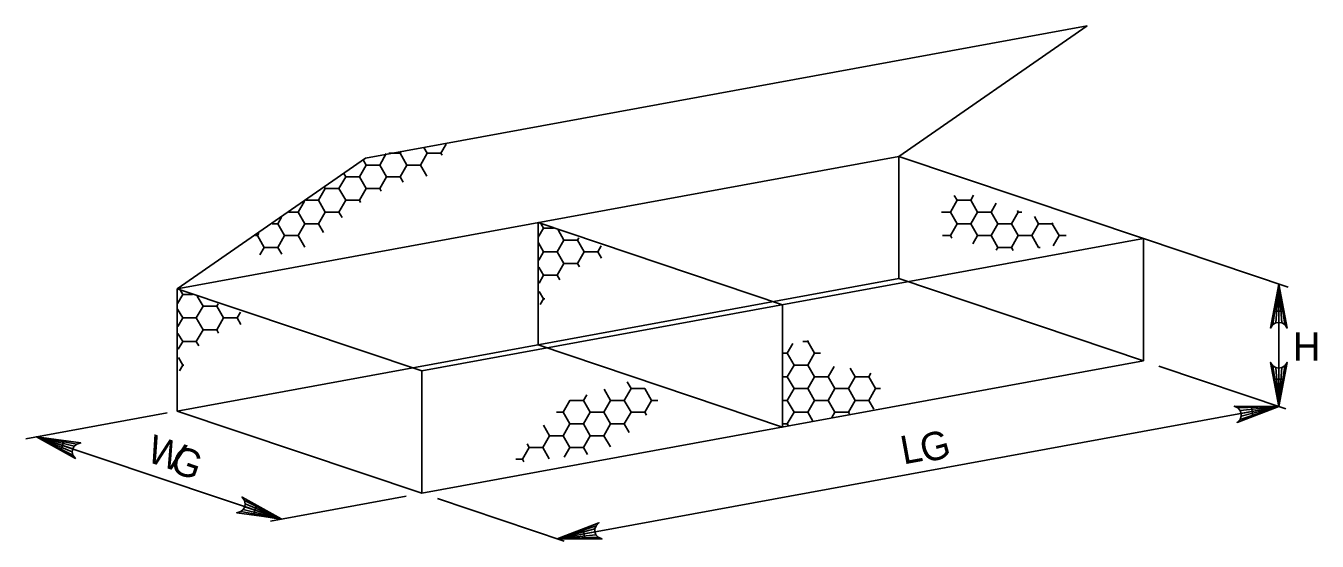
# Model space of a CAD drawing. Extents: x 638142 to 639291, y 297247 to 298438.
# Drawn here: x 638842.5 to 638979.6, y 297441.4 to 297496 of the extents above; entities that cross this region are included whole.
import ezdxf

# ---------------------------------------------------------------- set-up
doc = ezdxf.new("R2010")
doc.units = 0
doc.layers.add('3', color=7, linetype='Continuous')
doc.layers.add('5', color=7, linetype='Continuous')

msp = doc.modelspace()

# ---------------------------------------------------------------- linework, layer by layer
at = {"layer": '3'}
for p, q in [((638878.6, 297481.99), (638955.18, 297496.04)), ((638935.19, 297482.19), (638955.18, 297496.04)), ((638885.15, 297482.52), (638884.8, 297483.12)), ((638886.59, 297482.52), (638887.15, 297483.49)), ((638858.61, 297468.14), (638935.19, 297482.19)), ((638858.61, 297468.14), (638878.6, 297481.99)), ((638878.66, 297481.27), (638878.35, 297481.81)), ((638880.1, 297481.27), (638880.8, 297482.48)), ((638881.07, 297482.52), (638882.26, 297482.52)), ((638882.26, 297482.52), (638882.38, 297482.73)), ((638882.98, 297481.27), (638882.26, 297482.52)), ((638884.42, 297481.27), (638885.15, 297482.52)), ((638885.15, 297482.52), (638886.59, 297482.52)), ((638886.72, 297482.3), (638886.59, 297482.52)), ((638935.19, 297469.22), (638935.19, 297482.19)), ((638935.19, 297482.19), (638961.14, 297473.47)), ((638876.5, 297480.03), (638876.3, 297480.37)), ((638877.94, 297480.03), (638878.66, 297481.27)), ((638878.66, 297481.27), (638880.1, 297481.27)), ((638880.82, 297480.03), (638880.1, 297481.27)), ((638882.26, 297480.03), (638882.98, 297481.27)), ((638882.98, 297481.27), (638884.42, 297481.27)), ((638885.1, 297480.1), (638884.42, 297481.27)), ((638873.61, 297477.53), (638874.33, 297478.78)), ((638874.33, 297478.78), (638874.24, 297478.93)), ((638874.33, 297478.78), (638875.77, 297478.78)), ((638875.77, 297478.78), (638876.5, 297480.03)), ((638876.5, 297477.53), (638875.77, 297478.78)), ((638876.5, 297480.03), (638877.94, 297480.03)), ((638878.66, 297478.78), (638877.94, 297480.03)), ((638877.94, 297477.53), (638878.66, 297478.78)), ((638878.66, 297478.78), (638880.1, 297478.78)), ((638880.1, 297478.78), (638880.82, 297480.03)), ((638880.26, 297478.5), (638880.1, 297478.78)), ((638880.82, 297480.03), (638882.26, 297480.03)), ((638882.59, 297479.46), (638882.26, 297480.03)), ((638871.45, 297476.28), (638872.11, 297477.43)), ((638872.25, 297477.53), (638873.61, 297477.53)), ((638874.33, 297476.28), (638873.61, 297477.53)), ((638875.77, 297476.28), (638876.5, 297477.53)), ((638876.5, 297477.53), (638877.94, 297477.53)), ((638878.07, 297477.3), (638877.94, 297477.53)), ((638940.66, 297476.28), (638941.38, 297477.53)), ((638941.38, 297477.53), (638941.08, 297478.05)), ((638941.38, 297477.53), (638942.82, 297477.53)), ((638942.82, 297477.53), (638943.13, 297478.07)), ((638943.54, 297476.28), (638942.82, 297477.53)), ((638870.47, 297476.28), (638871.45, 297476.28)), ((638872.17, 297475.03), (638871.45, 297476.28)), ((638873.61, 297475.03), (638874.33, 297476.28)), ((638874.33, 297476.28), (638875.77, 297476.28)), ((638876.11, 297475.69), (638875.77, 297476.28)), ((638939.72, 297476.28), (638940.66, 297476.28)), ((638941.38, 297475.03), (638940.66, 297476.28)), ((638942.82, 297475.03), (638943.54, 297476.28)), ((638943.54, 297476.28), (638944.98, 297476.28)), ((638944.98, 297476.28), (638945.53, 297477.23)), ((638945.7, 297475.03), (638944.98, 297476.28)), ((638947.14, 297475.03), (638947.87, 297476.28)), ((638947.87, 297476.28), (638947.77, 297476.45)), ((638947.87, 297476.28), (638948.25, 297476.28)), ((638868.69, 297475.03), (638869.28, 297475.03)), ((638869.28, 297475.03), (638869.69, 297475.73)), ((638870.01, 297473.78), (638869.28, 297475.03)), ((638871.45, 297473.78), (638872.17, 297475.03)), ((638872.17, 297475.03), (638873.61, 297475.03)), ((638874.15, 297474.1), (638873.61, 297475.03)), ((638896.9, 297475.17), (638922.85, 297466.44)), ((638896.9, 297462.19), (638896.9, 297475.17)), ((638897.48, 297474.56), (638897.2, 297475.06)), ((638940.66, 297473.78), (638941.38, 297475.03)), ((638941.38, 297475.03), (638942.82, 297475.03)), ((638943.54, 297473.78), (638942.82, 297475.03)), ((638944.98, 297473.78), (638945.7, 297475.03)), ((638945.7, 297475.03), (638947.14, 297475.03)), ((638947.87, 297473.78), (638947.14, 297475.03)), ((638949.31, 297473.78), (638950.03, 297475.03)), ((638950.03, 297475.03), (638949.58, 297475.81)), ((638950.03, 297475.03), (638951.47, 297475.03)), ((638951.47, 297475.03), (638951.53, 297475.13)), ((638952.19, 297473.78), (638951.47, 297475.03)), ((638866.91, 297473.78), (638867.12, 297473.78)), ((638867.12, 297473.78), (638867.27, 297474.03)), ((638867.84, 297472.53), (638867.12, 297473.78)), ((638869.28, 297472.53), (638870.01, 297473.78)), ((638870.01, 297473.78), (638871.45, 297473.78)), ((638872.17, 297472.54), (638871.45, 297473.78)), ((638884.56, 297459.42), (638961.14, 297473.47)), ((638896.93, 297473.6), (638897.48, 297474.56)), ((638897.48, 297474.56), (638898.53, 297474.56)), ((638898.93, 297472.07), (638899.65, 297473.31)), ((638899.65, 297473.31), (638899.03, 297474.38)), ((638899.65, 297473.31), (638901.09, 297473.31)), ((638901.09, 297473.31), (638901.23, 297473.56)), ((638901.81, 297472.07), (638901.09, 297473.31)), ((638939.83, 297473.78), (638940.66, 297473.78)), ((638940.81, 297473.51), (638940.66, 297473.78)), ((638943.04, 297472.91), (638943.54, 297473.78)), ((638943.54, 297473.78), (638944.98, 297473.78)), ((638945.7, 297472.53), (638944.98, 297473.78)), ((638947.14, 297472.53), (638947.87, 297473.78)), ((638947.87, 297473.78), (638949.31, 297473.78)), ((638950.03, 297472.53), (638949.31, 297473.78)), ((638951.56, 297472.68), (638952.19, 297473.78)), ((638952.19, 297473.78), (638952.94, 297473.78)), ((638961.14, 297460.49), (638961.14, 297473.47)), ((638867.38, 297471.74), (638867.84, 297472.53)), ((638867.84, 297472.53), (638869.28, 297472.53)), ((638869.71, 297471.81), (638869.28, 297472.53)), ((638897.48, 297472.07), (638896.94, 297473.01)), ((638896.97, 297471.18), (638897.48, 297472.07)), ((638897.48, 297472.07), (638898.93, 297472.07)), ((638899.65, 297470.82), (638898.93, 297472.07)), ((638901.09, 297470.82), (638901.81, 297472.07)), ((638901.81, 297472.07), (638903.25, 297472.07)), ((638903.25, 297472.07), (638903.61, 297472.69)), ((638903.64, 297471.38), (638903.25, 297472.07)), ((638945.53, 297472.24), (638945.7, 297472.53)), ((638945.7, 297472.53), (638947.14, 297472.53)), ((638947.33, 297472.21), (638947.14, 297472.53)), ((638950.02, 297472.51), (638950.03, 297472.53)), ((638950.03, 297472.53), (638950.2, 297472.53)), ((638898.93, 297469.57), (638899.65, 297470.82)), ((638899.65, 297470.82), (638901.09, 297470.82)), ((638901.29, 297470.47), (638901.09, 297470.82)), ((638858.61, 297455.16), (638935.19, 297469.22)), ((638897.48, 297469.57), (638896.98, 297470.44)), ((638897.01, 297468.75), (638897.48, 297469.57)), ((638897.48, 297469.57), (638898.93, 297469.57)), ((638899.2, 297469.1), (638898.93, 297469.57)), ((638935.19, 297469.22), (638961.14, 297460.49)), ((638858.61, 297468.14), (638884.56, 297459.42)), ((638858.61, 297455.16), (638858.61, 297468.14)), ((638859.19, 297467.54), (638858.91, 297468.03)), ((638897.48, 297467.07), (638897.03, 297467.86)), ((638858.64, 297466.57), (638859.19, 297467.54)), ((638859.19, 297467.54), (638860.24, 297467.54)), ((638861.35, 297466.29), (638860.74, 297467.35)), ((638862.8, 297466.29), (638862.94, 297466.54)), ((638897.13, 297466.46), (638897.48, 297467.07)), ((638897.48, 297467.07), (638897.61, 297467.07)), ((638922.85, 297453.46), (638922.85, 297466.44)), ((638859.19, 297465.04), (638858.65, 297465.99)), ((638858.68, 297464.15), (638859.19, 297465.04)), ((638859.19, 297465.04), (638860.63, 297465.04)), ((638860.63, 297465.04), (638861.35, 297466.29)), ((638861.35, 297463.79), (638860.63, 297465.04)), ((638861.35, 297466.29), (638862.8, 297466.29)), ((638863.52, 297465.04), (638862.8, 297466.29)), ((638862.8, 297463.79), (638863.52, 297465.04)), ((638863.52, 297465.04), (638864.96, 297465.04)), ((638864.96, 297465.04), (638865.32, 297465.66)), ((638865.36, 297464.36), (638864.96, 297465.04)), ((638860.63, 297462.54), (638861.35, 297463.79)), ((638861.35, 297463.79), (638862.8, 297463.79)), ((638863, 297463.44), (638862.8, 297463.79)), ((638859.19, 297462.54), (638858.69, 297463.41)), ((638858.72, 297461.73), (638859.19, 297462.54)), ((638859.19, 297462.54), (638860.63, 297462.54)), ((638860.9, 297462.07), (638860.63, 297462.54)), ((638923.35, 297461.3), (638923.95, 297462.33)), ((638925, 297462.54), (638925.52, 297462.54)), ((638925.52, 297462.54), (638925.58, 297462.66)), ((638926.24, 297461.3), (638925.52, 297462.54)), ((638896.9, 297462.19), (638922.85, 297453.46)), ((638922.85, 297461.3), (638923.35, 297461.3)), ((638924.07, 297460.05), (638923.35, 297461.3)), ((638925.52, 297460.05), (638926.24, 297461.3)), ((638926.24, 297461.3), (638926.89, 297461.3)), ((638859.19, 297460.05), (638858.74, 297460.84)), ((638858.84, 297459.44), (638859.19, 297460.05)), ((638859.19, 297460.05), (638859.32, 297460.05)), ((638884.56, 297446.44), (638961.14, 297460.49)), ((638923.35, 297458.8), (638924.07, 297460.05)), ((638924.07, 297460.05), (638925.52, 297460.05)), ((638926.24, 297458.8), (638925.52, 297460.05)), ((638927.68, 297458.8), (638928.32, 297459.9)), ((638930.56, 297458.8), (638930.04, 297459.71)), ((638884.56, 297446.44), (638884.56, 297459.42)), ((638906.77, 297457.55), (638906.36, 297458.26)), ((638922.85, 297458.8), (638923.35, 297458.8)), ((638924.07, 297457.55), (638923.35, 297458.8)), ((638925.52, 297457.55), (638926.24, 297458.8)), ((638926.24, 297458.8), (638927.68, 297458.8)), ((638928.4, 297457.55), (638927.68, 297458.8)), ((638929.84, 297457.55), (638930.56, 297458.8)), ((638930.56, 297458.8), (638932.01, 297458.8)), ((638932.01, 297458.8), (638932.22, 297459.17)), ((638932.73, 297457.55), (638932.01, 297458.8)), ((638901.73, 297456.3), (638902.08, 297456.9)), ((638904.61, 297456.3), (638903.92, 297457.49)), ((638906.05, 297456.3), (638906.77, 297457.55)), ((638906.77, 297457.55), (638908.22, 297457.55)), ((638908.22, 297457.55), (638908.22, 297457.56)), ((638908.94, 297456.3), (638908.22, 297457.55)), ((638923.35, 297456.3), (638924.07, 297457.55)), ((638924.07, 297457.55), (638925.52, 297457.55)), ((638926.24, 297456.3), (638925.52, 297457.55)), ((638927.68, 297456.3), (638928.4, 297457.55)), ((638928.4, 297457.55), (638929.84, 297457.55)), ((638930.56, 297456.3), (638929.84, 297457.55)), ((638932.01, 297456.3), (638932.73, 297457.55)), ((638932.73, 297457.55), (638933.23, 297457.55)), ((638899.56, 297455.05), (638900.28, 297456.3)), ((638900.28, 297456.3), (638900.27, 297456.33)), ((638900.28, 297456.3), (638901.73, 297456.3)), ((638902.45, 297455.05), (638901.73, 297456.3)), ((638903.89, 297455.05), (638904.61, 297456.3)), ((638904.61, 297456.3), (638906.05, 297456.3)), ((638906.77, 297455.05), (638906.05, 297456.3)), ((638908.22, 297455.05), (638908.94, 297456.3)), ((638908.94, 297456.3), (638909.6, 297456.3)), ((638922.85, 297456.3), (638923.35, 297456.3)), ((638924.07, 297455.05), (638923.35, 297456.3)), ((638925.52, 297455.05), (638926.24, 297456.3)), ((638926.24, 297456.3), (638927.68, 297456.3)), ((638928.4, 297455.05), (638927.68, 297456.3)), ((638929.84, 297455.05), (638930.56, 297456.3)), ((638930.56, 297456.3), (638932.01, 297456.3)), ((638932.55, 297455.36), (638932.01, 297456.3)), ((638858.61, 297455.16), (638884.56, 297446.44)), ((638898.85, 297455.05), (638899.56, 297455.05)), ((638900.28, 297453.8), (638899.56, 297455.05)), ((638901.73, 297453.8), (638902.45, 297455.05)), ((638902.45, 297455.05), (638903.89, 297455.05)), ((638904.61, 297453.8), (638903.89, 297455.05)), ((638906.05, 297453.8), (638906.77, 297455.05)), ((638906.77, 297455.05), (638908.22, 297455.05)), ((638908.4, 297454.72), (638908.22, 297455.05)), ((638923.35, 297453.8), (638924.07, 297455.05)), ((638924.07, 297455.05), (638925.52, 297455.05)), ((638926.07, 297454.1), (638925.52, 297455.05)), ((638928.07, 297454.49), (638928.4, 297455.05)), ((638928.4, 297455.05), (638929.84, 297455.05)), ((638929.95, 297454.86), (638929.84, 297455.05)), ((638898.12, 297452.55), (638897.48, 297453.68)), ((638899.56, 297452.55), (638900.28, 297453.8)), ((638900.28, 297453.8), (638901.73, 297453.8)), ((638902.45, 297452.55), (638901.73, 297453.8)), ((638903.89, 297452.55), (638904.61, 297453.8)), ((638904.61, 297453.8), (638906.05, 297453.8)), ((638906.58, 297452.89), (638906.05, 297453.8)), ((638922.85, 297453.8), (638923.35, 297453.8)), ((638923.48, 297453.59), (638923.35, 297453.8)), ((638895.24, 297450.06), (638895.96, 297451.31)), ((638895.96, 297451.31), (638895.74, 297451.68)), ((638895.96, 297451.31), (638897.4, 297451.31)), ((638897.4, 297451.31), (638898.12, 297452.55)), ((638898.1, 297450.1), (638897.4, 297451.31)), ((638898.12, 297452.55), (638899.56, 297452.55)), ((638900.28, 297451.31), (638899.56, 297452.55)), ((638899.69, 297450.28), (638900.28, 297451.31)), ((638900.28, 297451.31), (638901.73, 297451.31)), ((638901.73, 297451.31), (638902.45, 297452.55)), ((638902.16, 297450.56), (638901.73, 297451.31)), ((638902.45, 297452.55), (638903.89, 297452.55)), ((638904.58, 297451.37), (638903.89, 297452.55)), ((638894.53, 297450.06), (638895.24, 297450.06)), ((638895.39, 297449.79), (638895.24, 297450.06))]:
    msp.add_line(p, q, dxfattribs=at)
at = {"layer": '5'}
for p, q in [((638961.14, 297473.47), (638976.52, 297468.3)), ((638975.52, 297455.66), (638975.52, 297468.63)), ((638962.8, 297459.93), (638976.26, 297455.41)), ((638898.94, 297441.61), (638975.52, 297455.66)), ((638857.54, 297454.97), (638842.55, 297452.22)), ((638843.67, 297452.44), (638869.63, 297443.72)), ((638868.5, 297443.49), (638882.9, 297446.13)), ((638886.22, 297445.88), (638899.68, 297441.36))]:
    msp.add_line(p, q, dxfattribs=at)
for points in [[(638975.52, 297468.63), (638976.39, 297463.97), (638976.14, 297464.33), (638975.83, 297464.52), (638975.52, 297464.57), (638975.21, 297464.52), (638974.89, 297464.33), (638974.65, 297463.97), (638975.52, 297468.63), (638974.89, 297464.33), (638975.21, 297464.52), (638975.52, 297468.63), (638975.52, 297464.57), (638975.83, 297464.52), (638975.52, 297468.63), (638976.14, 297464.33)], [(638975.52, 297455.66), (638974.65, 297460.32), (638974.89, 297459.96), (638975.21, 297459.77), (638975.52, 297459.72), (638975.83, 297459.77), (638976.14, 297459.96), (638976.39, 297460.32), (638975.52, 297455.66), (638976.14, 297459.96), (638975.83, 297459.77), (638975.52, 297455.66), (638975.52, 297459.72), (638975.21, 297459.77), (638975.52, 297455.66), (638974.89, 297459.96)], [(638975.52, 297455.66), (638971.09, 297453.96), (638971.4, 297454.27), (638971.53, 297454.61), (638971.52, 297454.92), (638971.41, 297455.22), (638971.17, 297455.5), (638970.78, 297455.68), (638975.52, 297455.66), (638971.17, 297455.5), (638971.41, 297455.22), (638975.52, 297455.66), (638971.52, 297454.92), (638971.53, 297454.61), (638975.52, 297455.66), (638971.4, 297454.27)], [(638843.67, 297452.44), (638848.37, 297451.79), (638847.95, 297451.66), (638847.68, 297451.43), (638847.52, 297451.15), (638847.48, 297450.83), (638847.55, 297450.48), (638847.81, 297450.13), (638843.67, 297452.44), (638847.55, 297450.48), (638847.48, 297450.83), (638843.67, 297452.44), (638847.52, 297451.15), (638847.68, 297451.43), (638843.67, 297452.44), (638847.95, 297451.66)], [(638869.63, 297443.72), (638864.93, 297444.37), (638865.35, 297444.5), (638865.62, 297444.73), (638865.78, 297445.01), (638865.82, 297445.33), (638865.75, 297445.68), (638865.49, 297446.03), (638869.63, 297443.72), (638865.75, 297445.68), (638865.82, 297445.33), (638869.63, 297443.72), (638865.78, 297445.01), (638865.62, 297444.73), (638869.63, 297443.72), (638865.35, 297444.5)], [(638898.94, 297441.61), (638903.37, 297443.31), (638903.06, 297443), (638902.93, 297442.66), (638902.93, 297442.34), (638903.04, 297442.04), (638903.28, 297441.77), (638903.68, 297441.59), (638898.94, 297441.61), (638903.28, 297441.77), (638903.04, 297442.04), (638898.94, 297441.61), (638902.93, 297442.34), (638902.93, 297442.66), (638898.94, 297441.61), (638903.06, 297443)]]:
    msp.add_lwpolyline(points, dxfattribs=at)
for points in [[(638975.04, 297465.75), (638976, 297465.75), (638975.52, 297468.63)], [(638976, 297458.54), (638975.04, 297458.54), (638975.52, 297455.66)], [(638972.6, 297455.61), (638972.77, 297454.66), (638975.52, 297455.66)], [(638846.29, 297451.05), (638846.59, 297451.96), (638843.71, 297452.43)], [(638866.69, 297444.16), (638867, 297445.07), (638869.58, 297443.69)], [(638901.86, 297441.65), (638901.69, 297442.6), (638898.94, 297441.61)]]:
    msp.add_lwpolyline(points, close=True, dxfattribs=at)

# ---------------------------------------------------------------- texts
msp.add_text('H', height=3, dxfattribs=at).set_placement((638977.02, 297460.51))
for s, rotation, p in [('W', 341.4175, (638855.21, 297449.87)), ('G', 15.1898, (638937.91, 297449.59)), ('G', 340.7467, (638857.69, 297448.8)), ('L', 10.3971, (638935.68, 297449.49))]:
    msp.add_text(s, height=3, rotation=rotation, dxfattribs=at).set_placement(p)

doc.saveas('drawing.dxf')
